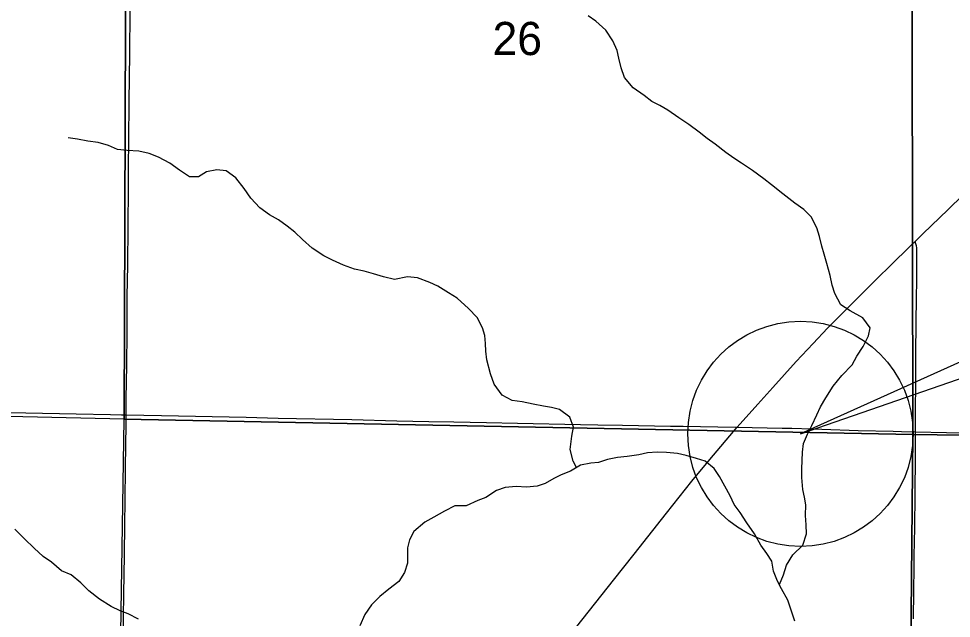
# Model space of a CAD drawing. Extents: x 0 to 34, y 0 to 22.
# Drawn here: x 3.588 to 4.764, y 15.338 to 16.094 of the extents above; entities that cross this region are included whole.
import ezdxf

# ---------------------------------------------------------------- set-up
doc = ezdxf.new("R2010")
doc.units = 0
for name, color, linetype in [('GM_X_Corporation', 7, 'Continuous'), ('GM_X_County_Road', 7, 'Continuous'), ('GM_X_Minor_River', 7, 'Continuous'), ('GM_X_Section_Text', 7, 'Continuous'), ('GM_X_State_Route', 7, 'Continuous'), ('GM_X_US_Route', 7, 'Continuous'), ('SH_Data', 7, 'Continuous')]:
    doc.layers.add(name, color=color, linetype=linetype)

msp = doc.modelspace()

# ---------------------------------------------------------------- linework, layer by layer
at = {"layer": 'GM_X_Corporation'}
for points in [[(2.7352, 16.6292), (3.7247, 16.5938), (3.7211, 15.5889), (2.718, 15.6121)], [(3.7247, 16.5938), (4.7141, 16.575), (4.7157, 15.5696), (3.7211, 15.5889)], [(4.7141, 16.575), (5.7459, 16.557), (5.726, 15.5556), (4.7157, 15.5696)], [(3.7211, 15.5889), (4.7157, 15.5696), (4.7065, 14.5692), (4.6846, 14.5697), (3.7059, 14.5912)], [(4.7157, 15.5696), (5.726, 15.5556), (5.7061, 14.5519), (4.7065, 14.5692)]]:
    msp.add_lwpolyline(points, close=True, dxfattribs=at)
at = {"layer": 'GM_X_County_Road'}
for points in [[(4.7186, 15.8132), (4.7288, 15.8231), (4.7596, 15.853), (4.8183, 15.9103), (4.84, 15.9317), (4.8761, 15.9669), (4.9636, 16.0526), (5.0072, 16.0951), (5.0319, 16.1188), (5.0648, 16.1509), (5.0824, 16.1685), (5.0919, 16.1775), (5.119, 16.204), (5.1199, 16.2049), (5.1663, 16.2499), (5.1899, 16.273)], [(4.4943, 15.5787), (4.52, 15.6076), (4.539, 15.6289), (4.5687, 15.6615), (4.5899, 15.6843), (4.6082, 15.7037), (4.6257, 15.7214), (4.6714, 15.7671), (4.687, 15.7823), (4.7132, 15.808), (4.7186, 15.8132)], [(4.7189, 15.5728), (4.7188, 15.583), (4.7191, 15.5998), (4.7193, 15.6333), (4.7195, 15.6501), (4.7196, 15.665), (4.7196, 15.6805), (4.7197, 15.701), (4.7199, 15.7184), (4.7201, 15.734), (4.7205, 15.7719), (4.7208, 15.7955), (4.7208, 15.7998), (4.7207, 15.8026), (4.7205, 15.8051), (4.7201, 15.8077), (4.7196, 15.81), (4.7186, 15.8132)], [(4.7165, 15.3369), (4.7169, 15.3717), (4.7172, 15.4022), (4.7174, 15.4146), (4.7178, 15.4357), (4.7181, 15.45), (4.7181, 15.4581), (4.7184, 15.4873), (4.7187, 15.5122), (4.7188, 15.5246), (4.7189, 15.5377), (4.7189, 15.5501), (4.7189, 15.5687), (4.7189, 15.5728)]]:
    msp.add_lwpolyline(points, dxfattribs=at)
at = {"layer": 'GM_X_Minor_River'}
for points in [[(4.5474, 15.3802), (4.5525, 15.3926), (4.5565, 15.4047), (4.5643, 15.4178), (4.5771, 15.4297), (4.5815, 15.444), (4.581, 15.4557), (4.5801, 15.4675), (4.5807, 15.4808), (4.579, 15.4903), (4.5769, 15.5002), (4.5757, 15.5154), (4.5755, 15.5264), (4.5761, 15.5366), (4.5767, 15.5472), (4.5777, 15.5582), (4.5828, 15.5699), (4.5883, 15.5807), (4.5947, 15.5943), (4.599, 15.6044), (4.6061, 15.616), (4.6151, 15.6307), (4.626, 15.6441), (4.6391, 15.6575), (4.645, 15.6684), (4.6528, 15.6804), (4.6599, 15.6939), (4.662, 15.7041), (4.6524, 15.7168), (4.6366, 15.7254), (4.6247, 15.7332), (4.6173, 15.7474), (4.6141, 15.7581), (4.6113, 15.7703), (4.6071, 15.7852), (4.6039, 15.797), (4.6011, 15.8073), (4.5979, 15.8195), (4.5947, 15.8305), (4.5874, 15.844), (4.5784, 15.8536), (4.5668, 15.8614), (4.5519, 15.8731), (4.5373, 15.8844), (4.5276, 15.8921), (4.5134, 15.9027), (4.4996, 15.912), (4.4898, 15.9183), (4.4797, 15.9253), (4.4666, 15.9358), (4.4562, 15.9432), (4.4461, 15.951), (4.4334, 15.9607), (4.4207, 15.9693), (4.4068, 15.9787), (4.3967, 15.9849), (4.3865, 15.9897), (4.3768, 15.9975), (4.363, 16.0072), (4.3522, 16.0199), (4.3479, 16.0321), (4.3451, 16.0443), (4.343, 16.0539), (4.3372, 16.0665), (4.3284, 16.0796), (4.3161, 16.0912), (4.3063, 16.0978)], [(4.2916, 15.528), (4.2875, 15.5357), (4.2836, 15.5506), (4.2859, 15.5676), (4.288, 15.5786), (4.2833, 15.5916), (4.2702, 15.6009), (4.26, 15.6038), (4.2498, 15.6051), (4.237, 15.6076), (4.223, 15.6109), (4.2105, 15.6123), (4.1977, 15.619), (4.1878, 15.6332), (4.1831, 15.6462), (4.1785, 15.6637), (4.1772, 15.6748), (4.177, 15.6842), (4.1761, 15.6945), (4.1732, 15.704), (4.1663, 15.7171), (4.1555, 15.7287), (4.141, 15.7414), (4.1301, 15.7481), (4.1166, 15.7567), (4.1068, 15.7614), (4.091, 15.7671), (4.0785, 15.7684), (4.0622, 15.7653), (4.0482, 15.7683), (4.0358, 15.7723), (4.0237, 15.7756), (4.0116, 15.7781), (3.9977, 15.7833), (3.9841, 15.7896), (3.9729, 15.7951), (3.9583, 15.8045), (3.946, 15.8157), (3.9363, 15.825), (3.9266, 15.8324), (3.9157, 15.8406), (3.9045, 15.8469), (3.8925, 15.8555), (3.881, 15.8678), (3.8725, 15.8801), (3.8621, 15.8936), (3.8498, 15.9022), (3.8381, 15.9035), (3.8251, 15.9011), (3.8151, 15.8945), (3.8038, 15.8947), (3.791, 15.9033), (3.7787, 15.9119), (3.7644, 15.9197), (3.7528, 15.9241), (3.7396, 15.9271), (3.7252, 15.9281), (3.7127, 15.9291), (3.7014, 15.9342), (3.6886, 15.9379), (3.6753, 15.9397), (3.6625, 15.9422), (3.6508, 15.9439)], [(4.524, 15.4299), (4.5159, 15.4441), (4.5063, 15.4579), (4.4979, 15.471), (4.4905, 15.4814), (4.4854, 15.4921), (4.4788, 15.5044), (4.4718, 15.5166), (4.4652, 15.5266), (4.4536, 15.5359), (4.4427, 15.5392), (4.4299, 15.5432), (4.4189, 15.5457), (4.4049, 15.5467), (4.3932, 15.5474), (4.381, 15.5464), (4.37, 15.544), (4.3555, 15.5416), (4.3434, 15.5404), (4.3308, 15.5379), (4.3193, 15.5344), (4.3095, 15.5334), (4.2965, 15.531), (4.2839, 15.5233), (4.2724, 15.5186), (4.2628, 15.5138), (4.2521, 15.5076), (4.2422, 15.5044), (4.2285, 15.5031), (4.2156, 15.5038), (4.2016, 15.5025), (4.1909, 15.4989), (4.1774, 15.4901), (4.1671, 15.4861), (4.1526, 15.4796), (4.1382, 15.4795), (4.1251, 15.4729), (4.1117, 15.4652), (4.1002, 15.459), (4.0867, 15.4471), (4.0812, 15.4366), (4.0787, 15.4264), (4.0784, 15.4071), (4.0747, 15.3954), (4.0677, 15.3841), (4.055, 15.3745), (4.0438, 15.3653), (4.033, 15.3545), (4.0248, 15.3425), (4.0184, 15.3279)], [(3.7395, 15.3367), (3.7264, 15.3434), (3.7162, 15.347), (3.7049, 15.3525), (3.6903, 15.3619), (3.6769, 15.3724), (3.6668, 15.3824), (3.6545, 15.3925), (3.6425, 15.3973), (3.6298, 15.4085), (3.6193, 15.4156), (3.6078, 15.426), (3.5955, 15.438), (3.5836, 15.45)], [(4.5669, 15.3339), (4.5622, 15.3477), (4.5579, 15.3603), (4.5502, 15.3748), (4.5451, 15.3844), (4.54, 15.397), (4.538, 15.4096), (4.5314, 15.4195), (4.524, 15.4299)]]:
    msp.add_lwpolyline(points, dxfattribs=at)
at = {"layer": 'GM_X_State_Route'}
msp.add_line((4.4943, 15.5787), (4.5508, 15.5776), dxfattribs=at)
for points in [[(3.7198, 15.282), (3.7206, 15.3384), (3.7209, 15.3682), (3.7217, 15.4173), (3.7223, 15.4565), (3.7226, 15.4857), (3.7231, 15.528), (3.7239, 15.5827), (3.7239, 15.5944), (3.7239, 15.6144), (3.7246, 15.6572), (3.7251, 15.6983), (3.7252, 15.7437), (3.7258, 15.7834), (3.7267, 15.881), (3.7269, 15.9071), (3.7273, 15.9401), (3.7277, 15.9898), (3.7283, 16.0501), (3.7287, 16.1036)], [(4.2839, 15.317), (4.3384, 15.3858), (4.3641, 15.4185), (4.4049, 15.4703), (4.4372, 15.5106), (4.4597, 15.5379), (4.4943, 15.5787)], [(4.5508, 15.5776), (4.5629, 15.5774), (4.5878, 15.5767)], [(4.5878, 15.5767), (4.6008, 15.5763), (4.6467, 15.5747), (4.6909, 15.5736), (4.7014, 15.5734), (4.7189, 15.5728)], [(4.7189, 15.5728), (4.758, 15.572), (4.7772, 15.5716), (4.8518, 15.57), (4.896, 15.5691), (4.937, 15.5682), (4.9842, 15.5672), (5.0184, 15.5664), (5.0551, 15.5656), (5.0774, 15.565), (5.1402, 15.5637), (5.193, 15.5627), (5.2235, 15.562), (5.2944, 15.5608), (5.3677, 15.5592), (5.4423, 15.558), (5.51, 15.5566), (5.5865, 15.555), (5.6126, 15.5546), (5.6747, 15.5533), (5.7046, 15.5527), (5.729, 15.5524)]]:
    msp.add_lwpolyline(points, dxfattribs=at)
at = {"layer": 'GM_X_US_Route'}
msp.add_line((4.4943, 15.5787), (4.5508, 15.5776), dxfattribs=at)
for points in [[(3.5543, 15.5975), (3.6607, 15.5956), (3.7042, 15.5947), (3.7178, 15.5945), (3.7239, 15.5944)], [(3.7239, 15.5944), (3.7683, 15.5937), (3.8752, 15.5912), (3.9156, 15.5903), (4.0083, 15.5884), (4.0649, 15.5869), (4.1053, 15.586), (4.137, 15.5855), (4.178, 15.5847), (4.2172, 15.5839), (4.2968, 15.5821), (4.3186, 15.5817), (4.3497, 15.5813), (4.3696, 15.581), (4.41, 15.5801), (4.4262, 15.5799)], [(4.4262, 15.5799), (4.4697, 15.5792), (4.4943, 15.5787)], [(4.5508, 15.5776), (4.5629, 15.5774), (4.5878, 15.5767)], [(4.5878, 15.5767), (4.6008, 15.5763), (4.6467, 15.5747), (4.6909, 15.5736), (4.7014, 15.5734), (4.7189, 15.5728)], [(4.7189, 15.5728), (4.758, 15.572), (4.7772, 15.5716), (4.8518, 15.57), (4.896, 15.5691), (4.937, 15.5682), (4.9842, 15.5672), (5.0184, 15.5664), (5.0551, 15.5656), (5.0774, 15.565), (5.1402, 15.5637), (5.193, 15.5627), (5.2235, 15.562), (5.2944, 15.5608), (5.3677, 15.5592), (5.4423, 15.558), (5.51, 15.5566), (5.5865, 15.555), (5.6126, 15.5546), (5.6747, 15.5533), (5.7046, 15.5527), (5.729, 15.5524)]]:
    msp.add_lwpolyline(points, dxfattribs=at)
at = {"layer": 'SH_Data'}
msp.add_lwpolyline([(4.574, 15.5703), (9.2813, 17.2011), (9.2813, 17.6911)], close=True, dxfattribs=at)
msp.add_circle((4.574, 15.5703), 0.1421, dxfattribs=at)

# ---------------------------------------------------------------- texts
at = {"layer": 'GM_X_Section_Text'}
msp.add_text('26', height=0.04186, rotation=0, dxfattribs=at).set_placement((4.1858, 16.0483))

doc.saveas('drawing.dxf')
